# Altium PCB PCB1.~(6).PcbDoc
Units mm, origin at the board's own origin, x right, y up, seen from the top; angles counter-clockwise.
Board outline 70 x 70 mm, 4 copper layers (Top Layer, Internal Plane 1, Internal Plane 2, Bottom Layer), stack 0.462 mm thick; 13 components, 15 nets, 56 pads, 0 vias.
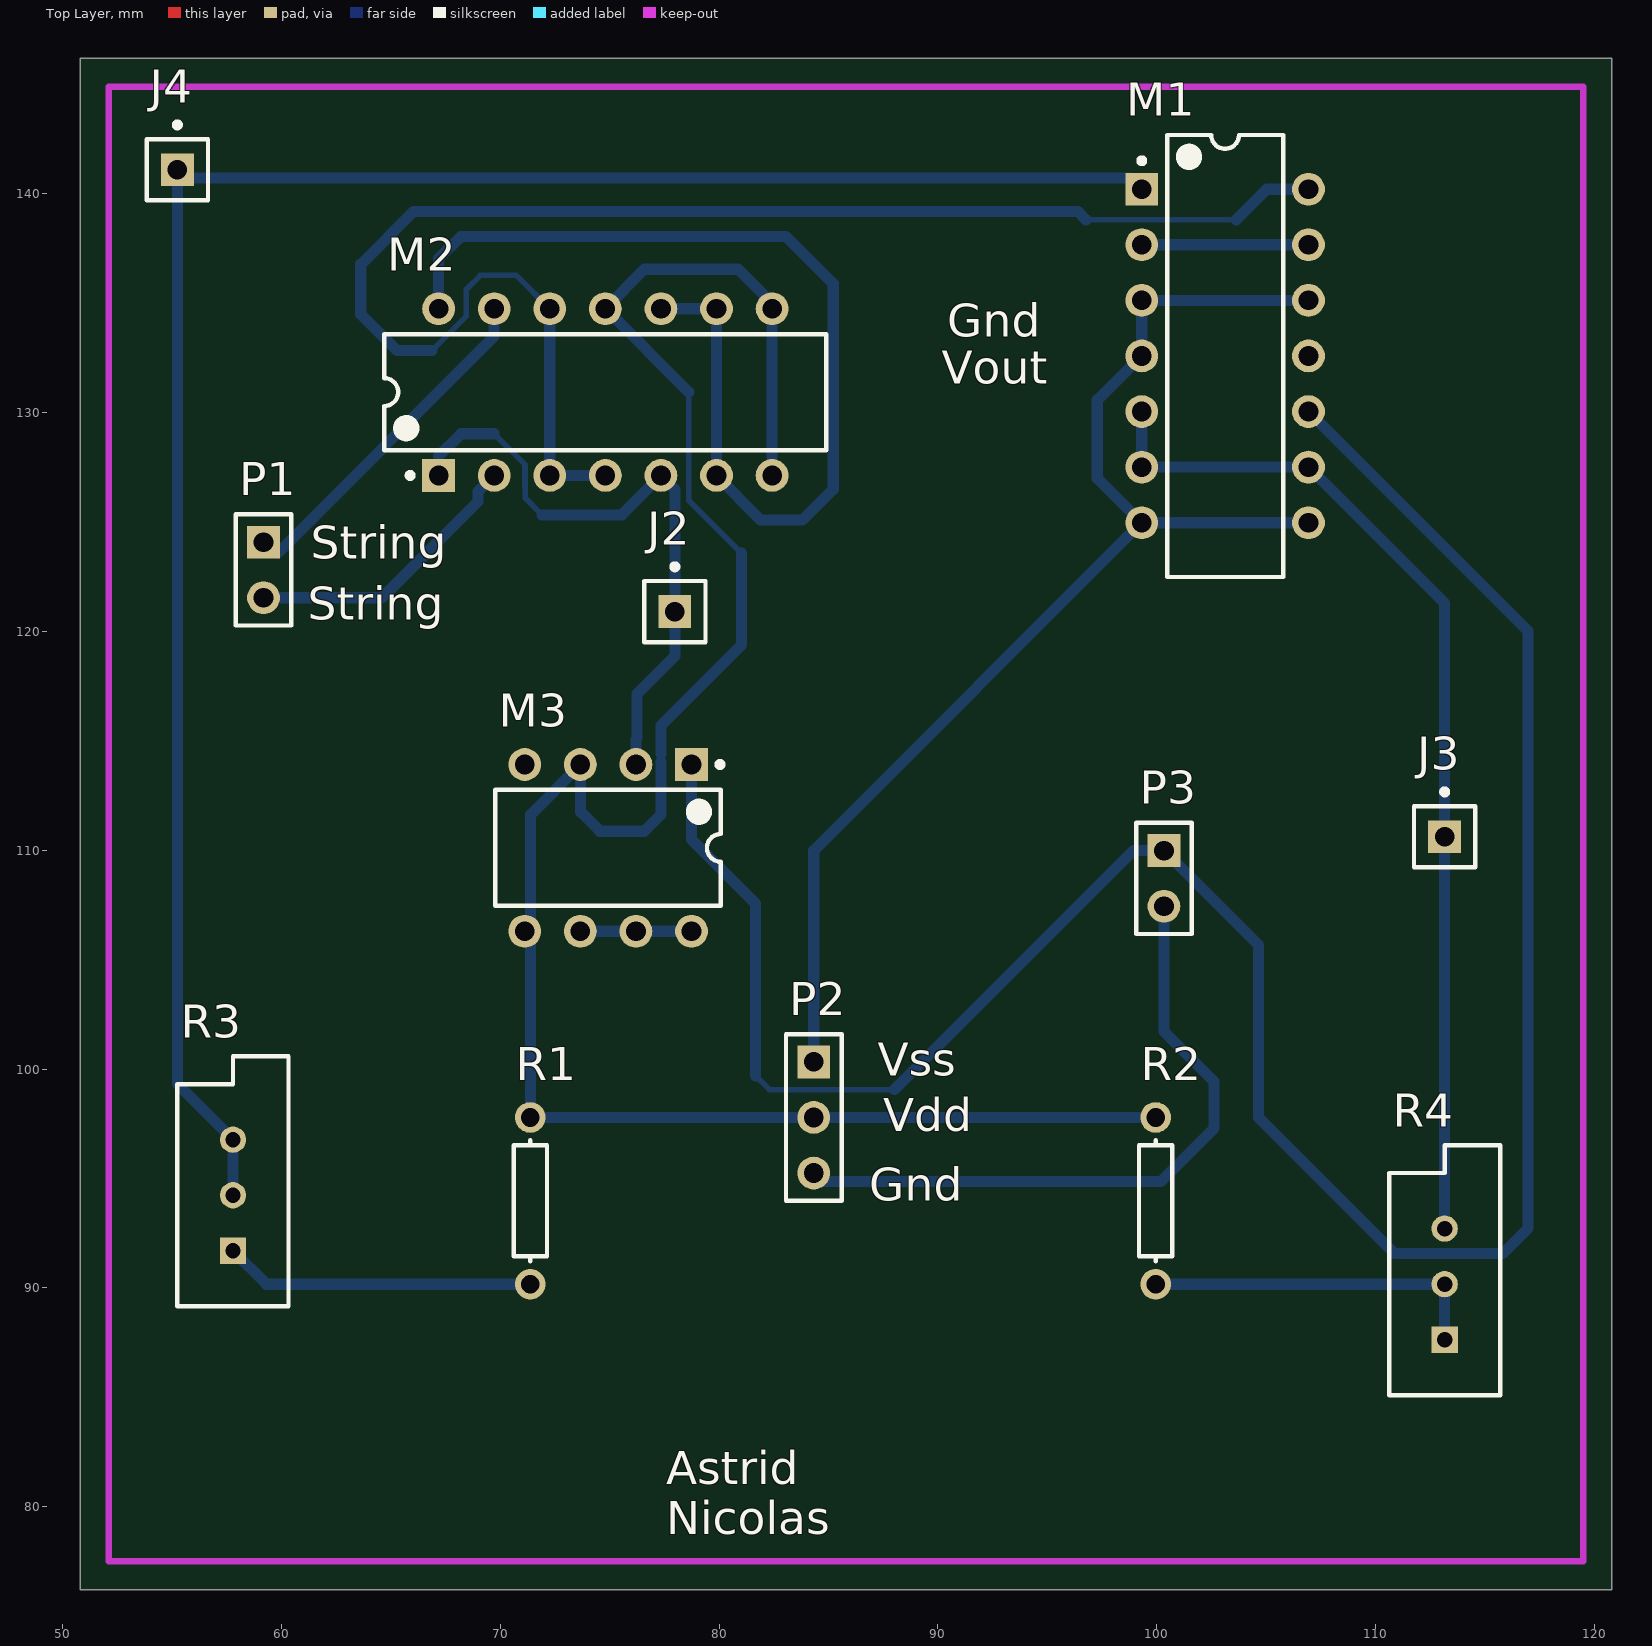
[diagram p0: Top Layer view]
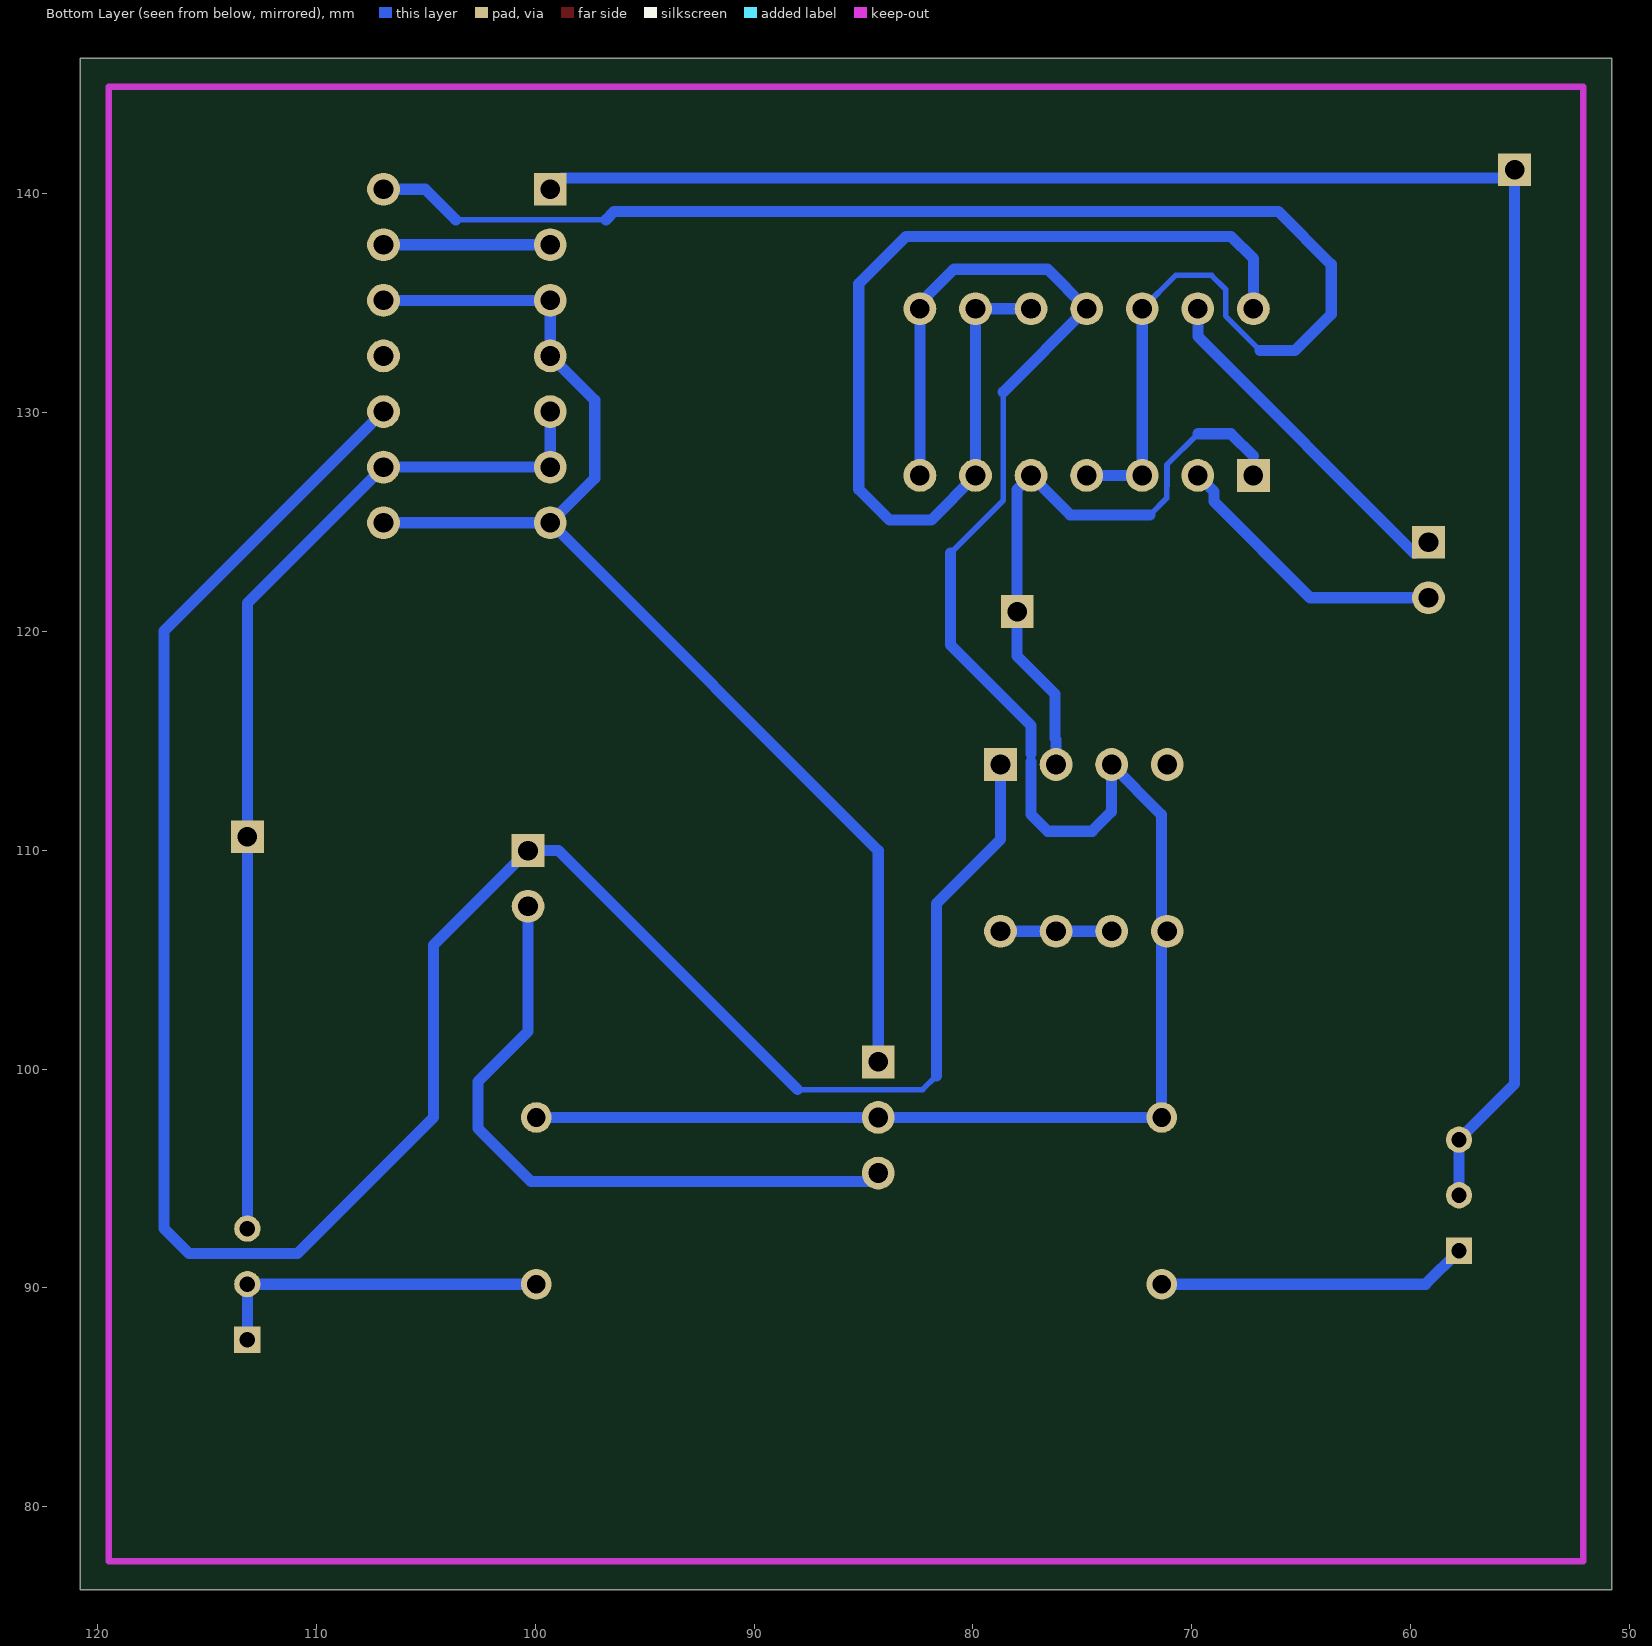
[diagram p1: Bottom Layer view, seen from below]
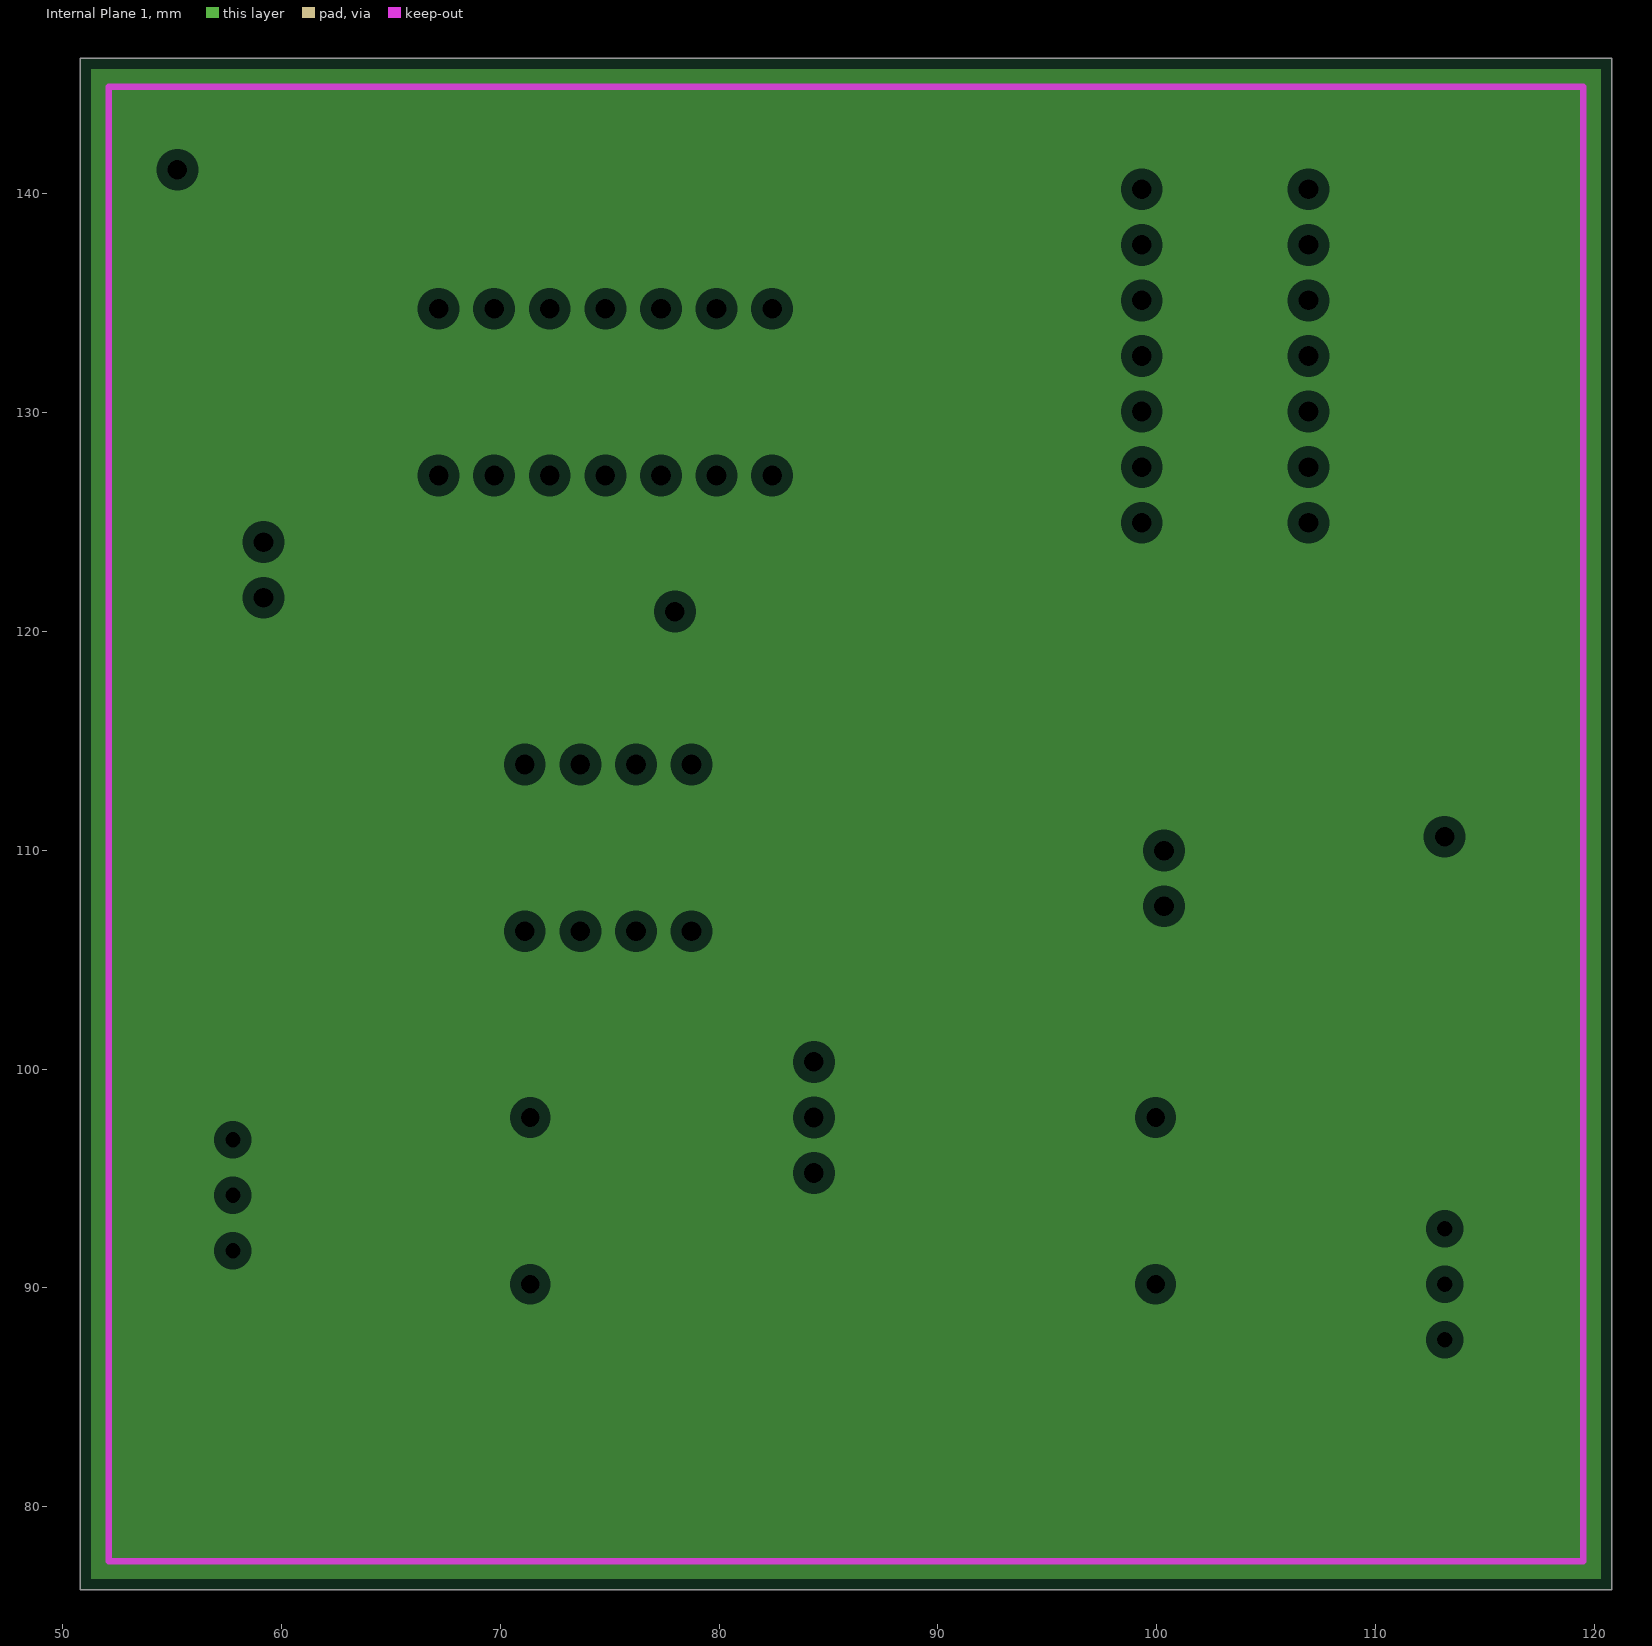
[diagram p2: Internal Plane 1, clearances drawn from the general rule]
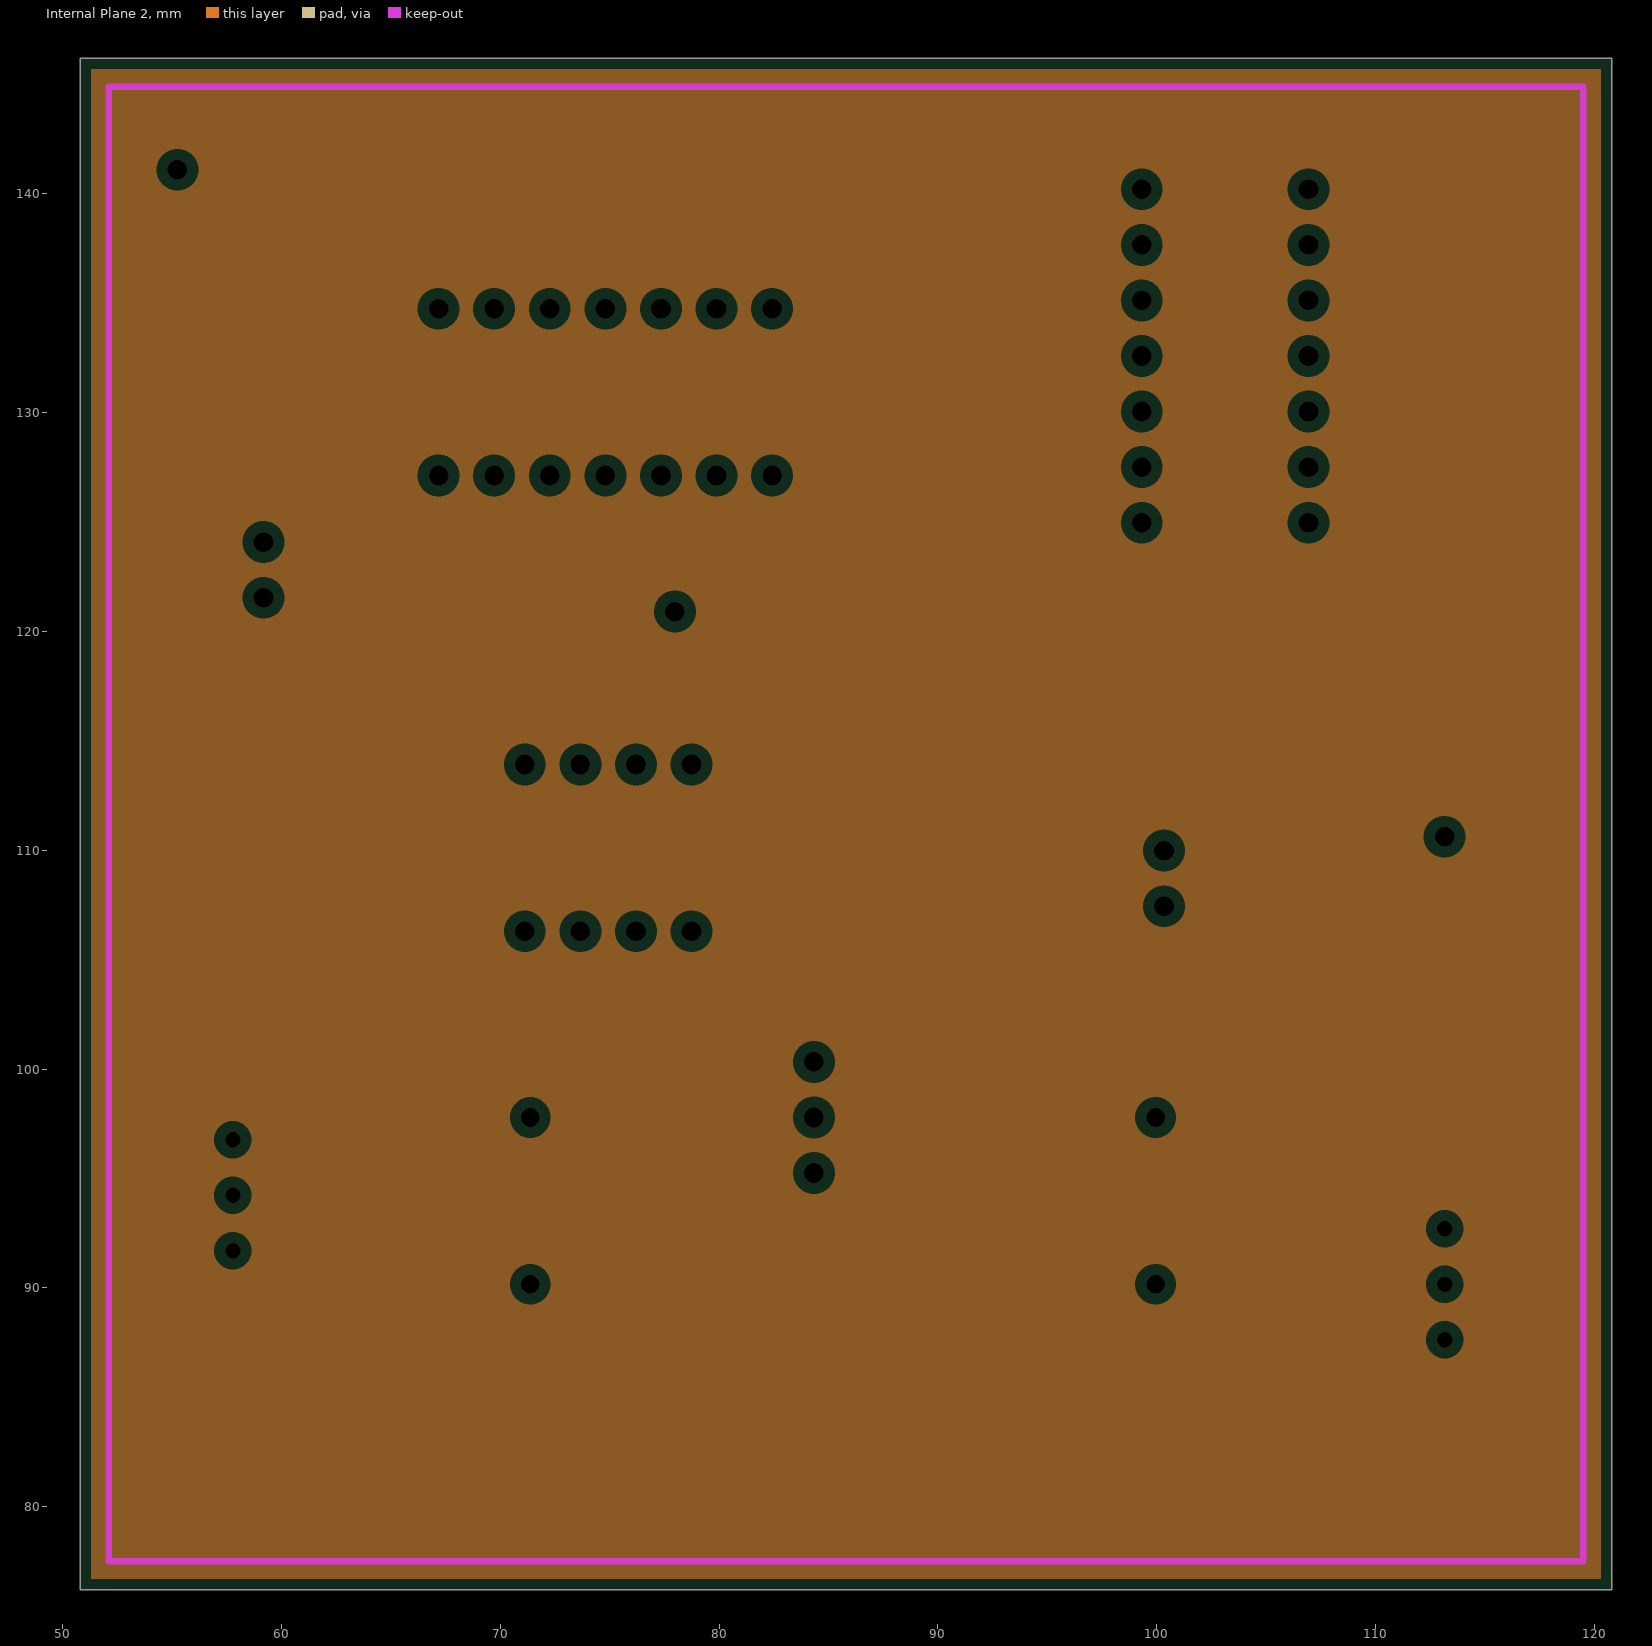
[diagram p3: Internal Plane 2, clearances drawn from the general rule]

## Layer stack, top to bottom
Top Solder: solder mask 0.0102, Solder Resist, Dk 3.5
Top Layer: signal copper 0.0356
Internal Plane 1: plane copper 0.0356
Internal Plane 2: plane copper 0.0356
Dielectric 1: dielectric 0.32, FR-4, Dk 4.8
Bottom Layer: signal copper 0.0356
Bottom Solder: solder mask 0.0102, Solder Resist, Dk 3.5

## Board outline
50.8,76.2 120.8,76.2 120.8,146.2 50.8,146.2

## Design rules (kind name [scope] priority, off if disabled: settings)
Clearance Clearance_2 [(InNet('VDD') OR InNet('NetM1_14') OR InNet('NetJ2_1'))] p1: gap=0.127
Clearance Clearance_1 [InNet('VOUT')] p2: gap=0.127
Clearance [All] p3: gap=0.8
PlaneClearance [All] p1: clearance=0.508
PlaneConnect [All] p1: planeconnectstyle=Relief reliefexpansion=0.508 reliefentries=4 reliefconductorwidth=0.254 reliefairgap=0.254
PolygonConnect [All] p1: connectstyle=Relief reliefconductorwidth=0.254 reliefentries=4 polygonreliefangle="90 Angle" airgapwidth=0.254
RoutingLayers [All] p1: top layer_v5=FALSE bottom layer_v5=TRUE
RoutingVias [All] p1: holewidth=0.8 width=1.6 viastyle="Through Hole" minholewidth=0.711 minwidth=1.27 maxholewidth=0.711 maxwidth=1.27
SolderMaskExpansion [All] p1: expansion=0.102
Width [All] p1: maxlimit=0.508 minlimit=0.5 preferedwidth=0.508 toplayer_maxwidth=0.5 toplayer_prefwidth=0.5 bottomlayer_minwidth=0.508 minimp=50.000000 maximp=50.000000 favimp=50.000000
27 further rules are at their usual default settings.

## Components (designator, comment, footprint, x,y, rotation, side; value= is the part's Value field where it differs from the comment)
J2 "Socket" PIN1 77.978,120.904 r0 top
J3 "Socket" PIN1 113.157,110.617 r0 top
J4 "Socket" PIN1 55.245,141.097 r0 top
M1 "ALD1106" DIP-14 103.124,132.588 r0 top
M2 "ALD1105" DIP-14 74.803,130.937 r90 top
M3 "ALD1117" DIP-8 74.93,110.109 r270 top
P1 "Header 2" HDR1X2 59.182,124.079 r270 top
P2 "Header 3" HDR1X3 84.328,100.33 r270 top
P3 "Header 2" HDR1X2 100.33,109.982 r270 top
R1 "Res1" AXIAL-0.3 71.374,93.98 r90 top
R2 "Res1" AXIAL-0.3 99.949,93.98 r90 top
R3 "RPot" VR5 57.785,94.234 r90 top
R4 "RPot" VR5 113.157,90.17 r90 top

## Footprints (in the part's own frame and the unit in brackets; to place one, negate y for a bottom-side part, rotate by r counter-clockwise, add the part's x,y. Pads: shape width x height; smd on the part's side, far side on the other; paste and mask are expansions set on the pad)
AXIAL-0.3 [mm] "Axial Device, Thru-Hole; 2 Leads; 0.3 in Pin Spacing"
  round 1.4 hole 0.85: 1(-3.81,0) 2(3.81,0)
  silkscreen extent -2.77,-0.76 2.77,0.76
DIP-8 [mm] "DIP, 8-Pin, Row Spacing 7.62 mm, Pitch 2.54 mm"
  rect 1.5x1.5 hole 0.9: 1(-3.81,3.81)
  round 1.5 hole 0.9: 2(-3.81,1.27) 3(-3.81,-1.27) 4(-3.81,-3.81) 5(3.81,-3.81) 6(3.81,-1.27) 7(3.81,1.27) 8(3.81,3.81)
  silkscreen extent -3.93,-5.15 2.65,5.24, body extent -3.6,-5.15 3.6,5.15, height 5.33
DIP-14 [mm] "DIP, 14-Pin, Row Spacing 7.62 mm, Pitch 2.54 mm"
  rect 1.5x1.5 hole 0.9: 1(-3.81,7.62)
  round 1.5 hole 0.9: 2(-3.81,5.08) 3(-3.81,2.54) 4(-3.81,0) 5(-3.81,-2.54) 6(-3.81,-5.08) 7(-3.81,-7.62) 8(3.81,-7.62) 9(3.81,-5.08) 10(3.81,-2.54) 11(3.81,0) 12(3.81,2.54) 13(3.81,5.08) 14(3.81,7.62)
  silkscreen extent -3.93,-10.1 2.65,10.1, body extent -3.6,-10.1 3.6,10.1, height 5.08
HDR1X2 [mm] "Connector; Header; 2 Position"
  rect 1.5x1.5 hole 0.9: 1(0,0)
  round 1.5 hole 0.9: 2(2.54,0)
  silkscreen extent -1.27,-1.27 3.81,1.27
HDR1X3 [mm] "Connector; Header; 3 Position"
  rect 1.5x1.5 hole 0.9: 1(0,0)
  round 1.5 hole 0.9: 2(2.54,0) 3(5.08,0)
  silkscreen extent -1.27,-1.27 6.35,1.27
PIN1 [mm] "Connector; Plug"
  rect 1.5x1.5 hole 0.9: 1(0,0)
  silkscreen extent -1.4,-1.4 1.4,2.17
VR5 [mm] "Thru-Hole; 3 Leads"
  rect 1.2x1.2 hole 0.7: 1(-2.54,0)
  round 1.2 hole 0.7: 2(0,0) 3(2.54,0)
  silkscreen extent -5.08,-2.54 6.35,2.54

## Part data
M1: "Quad N-channel matched MOSFET array"
M2: "Dual P-channel and dual N-channel matched MOSFET array"
M3: "Dual P-channel matched MOSFET array"
P1 P3: "Header, 2-Pin"
P2: "Header, 3-Pin"
R1 R2: "Resistor"
R3 R4: "Potentiometer"

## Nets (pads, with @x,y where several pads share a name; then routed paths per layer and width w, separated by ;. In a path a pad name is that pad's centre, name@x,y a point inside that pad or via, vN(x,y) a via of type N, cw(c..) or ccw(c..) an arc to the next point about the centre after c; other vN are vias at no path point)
GND: P2.3 P3.2 | length 30
  Bottom Layer w0.508: P2.3@84.709,94.869 100.203,94.869 102.616,97.282 102.616,99.441 100.33,101.727 P3.2
IN+: M2.2 P1.2 | length 13.1
  Bottom Layer w0.508: P1.2 64.586,121.539 68.987,125.94 68.987,126.391 M2.2
IN-: M2.13 P1.1 | length 15.3
  Bottom Layer w0.508: P1.1@59.817,123.571 69.723,133.477 M2.13
NetJ2_1: J2.1 M2.1 M2.5 M3.2 | length 27.9
  Bottom Layer w0.254: 69.723,129.032 71.146,127.609 ; 71.132,126.659 71.132,127.595 ; 71.146,126.645 71.146,126.085 71.908,125.323
  Bottom Layer w0.508: 67.183,128.016 68.199,129.032 69.723,129.032 ; 71.908,125.323 75.55,125.323 77.343,127.116 M2.5 77.978,126.492 J2.1 77.978,118.872 76.244,117.138 76.244,115.106 76.2,115.062 M3.2
NetJ3_1: J3.1 M1.5 M1.6 M1.9 R4.3 | length 47.5
  Bottom Layer w0.508: M1.5 M1.6 M1.9 106.945,127.508 113.157,121.296 J3.1 R4.3
NetJ4_1: J4.1 M1.1 R3.2 R3.3 | length 92.4
  Bottom Layer w0.508: R3.2 R3.3 55.245,99.314 J4.1 55.626,140.716 98.806,140.716 M1.1
NetM1_2: M1.2 M1.13 | length 7.6
  Bottom Layer w0.508: M1.2 M1.13
NetM1_14: M1.14 M2.3 M2.4 M2.12 | length 69.6
  Bottom Layer w0.254: 66.877,132.842 68.453,134.418 68.453,135.636 69.088,136.271 70.739,136.271 M2.12 ; 96.774,138.811 103.632,138.811
  Bottom Layer w0.508: 66.877,132.842 65.278,132.842 63.627,134.493 63.627,136.779 66.04,139.192 96.393,139.192 96.774,138.811 ; M2.12 M2.3 M2.4 ; 103.632,138.811 105.029,140.208 M1.14
NetM2_6: M2.6 M2.9 M2.10 M2.14 | length 47.9
  Bottom Layer w0.508: M2.14 67.183,137.033 68.199,138.049 83.058,138.049 85.217,135.89 85.217,126.492 83.82,125.095 81.904,125.095 M2.6@79.883,127.116 ; M2.10 M2.9 M2.6
NetM3_5: M3.6 M3.7 M3.8 | length 5.1
  Bottom Layer w0.508: M3.6 M3.7 M3.8
NetR1_1: R1.1 R3.1 | length 14.2
  Bottom Layer w0.508: R3.1 59.309,90.17 R1.1
NetR2_1: R2.1 R4.1 R4.2 | length 15.7
  Bottom Layer w0.508: R2.1 R4.2 R4.1
VDD: M2.7 M2.8 M2.11 M3.3 M3.5 P2.2 R1.2 R2.2 | length 95.9
  Bottom Layer w0.254: 78.613,130.937 78.613,125.984 81.026,123.571
  Bottom Layer w0.508: M3.3 M3.3@73.66,113.908 ; M2.11 78.613,130.937 ; M2.11@74.803,134.758 76.596,136.551 80.873,136.551 82.423,135.001 M2.8 M2.7 ; 77.343,114.046 77.343,111.633 76.581,110.871 74.549,110.871 73.66,111.76 M3.3@73.66,113.908 ; 77.343,114.392 77.343,115.697 81.026,119.38 81.026,123.571 ; R2.2 P2.2 R1.2 71.374,111.622 M3.3@73.66,113.908
VOUT: M1.10 M3.1 P3.1 | length 109.7
  Bottom Layer w0.254: 81.661,99.695 82.296,99.06 88.011,99.06
  Bottom Layer w0.508: M3.1 78.74,110.49 81.661,107.569 81.661,99.695 ; 88.011,99.06 98.933,109.982 P3.1 104.648,105.664 104.648,97.79 110.871,91.567 115.824,91.567 116.967,92.71 116.967,120.026 106.945,130.048 M1.10
VSS: M1.3 M1.4 M1.7 M1.8 M1.12 P2.1 | length 57.9
  Bottom Layer w0.508: P2.1 84.328,109.982 M1.7 ; M1.4@99.303,132.588 97.282,130.567 97.282,126.989 99.303,124.968 M1.7 ; M1.4 M1.3 M1.12 ; M1.8 M1.7
pads on no net: M1.11 M3.4

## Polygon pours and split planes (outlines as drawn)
GND on Bottom Layer "Bottom ground layer" (solid, shelved, pour order 2): 52.1,144.9 119.38,144.9 119.5,144.78 119.5,77.5 52.1,77.5

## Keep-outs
Keep-Out Layer:
  lines w0.3: 52.1,77.5 119.5,77.5 119.5,144.9 52.1,144.9 52.1,77.5

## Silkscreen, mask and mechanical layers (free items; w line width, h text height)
Top Overlay:
  text "Gnd" at 90.424,133.477 h1.52
  text "Vout" at 90.17,131.318 h1.52
  text "String" at 61.341,123.317 h1.52
  text "String" at 61.214,120.523 h1.52
  text "Vss" at 87.249,99.695 h1.52
  text "Vdd" at 87.503,97.155 h1.52
  text "Gnd" at 86.868,93.98 h1.52
  text "Astrid / Nicolas" at 77.597,78.74 h1.52

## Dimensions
52.1,77.5 to 119.5,77.5 on Mechanical 1
52.1,77.5 to 52.1,144.9 on Mechanical 1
